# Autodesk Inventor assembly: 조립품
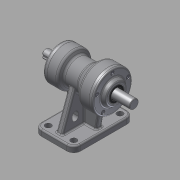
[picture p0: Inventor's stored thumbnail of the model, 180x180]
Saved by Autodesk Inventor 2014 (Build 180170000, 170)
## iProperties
Created: 2015-08
Part Number: 조립품
Document SubType Name: Assembly
Designer: USER
Author: USER
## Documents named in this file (10)
- C:\Users\USER\Desktop\450805V1009\조립품.iam
- C:\Users\USER\Desktop\450805V1009\본체.ipt
- C:\Users\USER\Desktop\450805V1009\M4x0.5.ipt
- C:\Users\USER\Desktop\450805V1009\뒤커버.ipt
- C:\Users\USER\Desktop\450805V1009\베어링 6203.ipt
- C:\Users\USER\Desktop\450805V1009\베어링 6205.ipt
- C:\Users\USER\Desktop\450805V1009\앞커버.ipt
- C:\Users\USER\Desktop\450805V1009\오일실 .ipt
- 오일실 .ipt
- C:\Users\USER\Desktop\450805V1009\축.ipt
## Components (10 placed, 1 different names)
1. M4x0.5:1
2. M4x0.5:3
3. M4x0.5:4
4. M4x0.5:5
5. M4x0.5:6
6. M4x0.5:2
7. M4x0.5:7
8. M4x0.5:8
9. M4x0.5:9
10. M4x0.5:10
